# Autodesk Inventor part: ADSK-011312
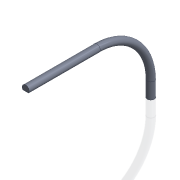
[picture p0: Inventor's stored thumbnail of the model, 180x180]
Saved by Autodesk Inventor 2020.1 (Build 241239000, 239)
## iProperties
Created: 1999-12
Part Number: ADSK-011312
Description: SHFT-M,RS,CP,PLOW
Document SubType Name: Modeling
Designer: tgregory
Material: Pearson Stainless Steel
Density: 8.03 g/cm^3
Appearance: Pearson-Stainless
Mass: 143.216 g
Surface Area: 76.1113 cm^2
Volume: 17.8351 cm^3
Control State: 0
Checked Out: False
Last Check In By: sspink
Last Check In Date: 1999-12-22
Master: False
Shininess: 57.0
Length Units: 11269
Angle Units: 11279
Time Units: 11290
Mass Units: 11283
Length Display Precision: 3
Angle Display Precision: 2
Compacted: True
Dimensions: 10x103x181 mm
Mass: 0,143 kg
Density: 8.03
Volumn: 16.559095710214205
Area: 73.36889043489425
PropertySet Name: Model Information
Author: tgregory
Revision Number: -
Title: SHFT-M,RS,CP,PLOW
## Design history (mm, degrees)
node "Solide1"
  node "Extrusion1" dims "d1" = 100, "d2" = 0
  node "Extrusion2" dims "d4" = 114.3, "d5" = 0
  node "Revolution1" dims "d8" = 90 deg
  node "Extrusion3" dims "d9" = 22, "d10" = 0
sketch "Sketch1"
  geometry: C1 r 5 at (0, 0)
  constraints: 1 centre point
  dimensions: "d0" = 10 diameter of C1
sketch "Sketch2"
  geometry: L1 (-4, -3)-(4, -3); A1 r 5 centre (0, 0) between (-4, -3) and (4, -3) reference
  constraints: 2 end point, 2 point on circle, 1 horizontal
  dimensions: "d3" = 8 dimension on A1 L1
workplane "Work Plane1"
workplane "Work Plane2"
workplane "Work Plane3"
workaxis "Work Axis1"
sketch "Sketch3"
  geometry: L1 (7, -75.962)-(-7, -75.962) reference; C1 r 5 at (0, 0) reference
workplane "Work Plane4"
node "Corps solides"
node "Corps surfaciques"
sketch "Sketch4"
  geometry: C1 r 5 at (0, 0) reference
other parameters: "d6" = -80.9625, "d7" = 0, "d11" = -80.9625
